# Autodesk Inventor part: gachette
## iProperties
Shininess: 20.0
Angle Display Precision: 2
Document Length Units: 11269
Document Angle Units: 11279
Document Time Units: 11290
Document Mass Units: 11283
Document Length Units Precision: 3
Document Angle Units Precision: 2
Compacted: True
Created: 2002-04
Part Number: gachette
Material: Par défaut
Document SubType Name: Modélisation
Designer: thchene
Density: 0.0
Volumn: 0.0
Area: 0.0
PropertySet Name: Model Information
Control State: 0
Master: False
Checked Out: False
Author: thchene
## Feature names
1. Extrusion1
2. Extrusion4
3. Extrusion5
4. Congé1 [Fillet]
5. Congé2 [Fillet]
6. Congé3 [Fillet]
7. Symétrie1 [Mirror]
8. Chanfrein1 [Chamfer]
9. Congé6 [Fillet]
10. Congé7 [Fillet]
